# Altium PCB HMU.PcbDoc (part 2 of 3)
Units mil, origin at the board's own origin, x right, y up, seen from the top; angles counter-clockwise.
Board outline 6247.81 x 4035.43 mil, 4 copper layers (Top Layer, Mid-Layer 1, Mid-Layer 2, Bottom Layer), stack 90 mil thick; 310 components, 201 nets, 779 pads, 176 vias.
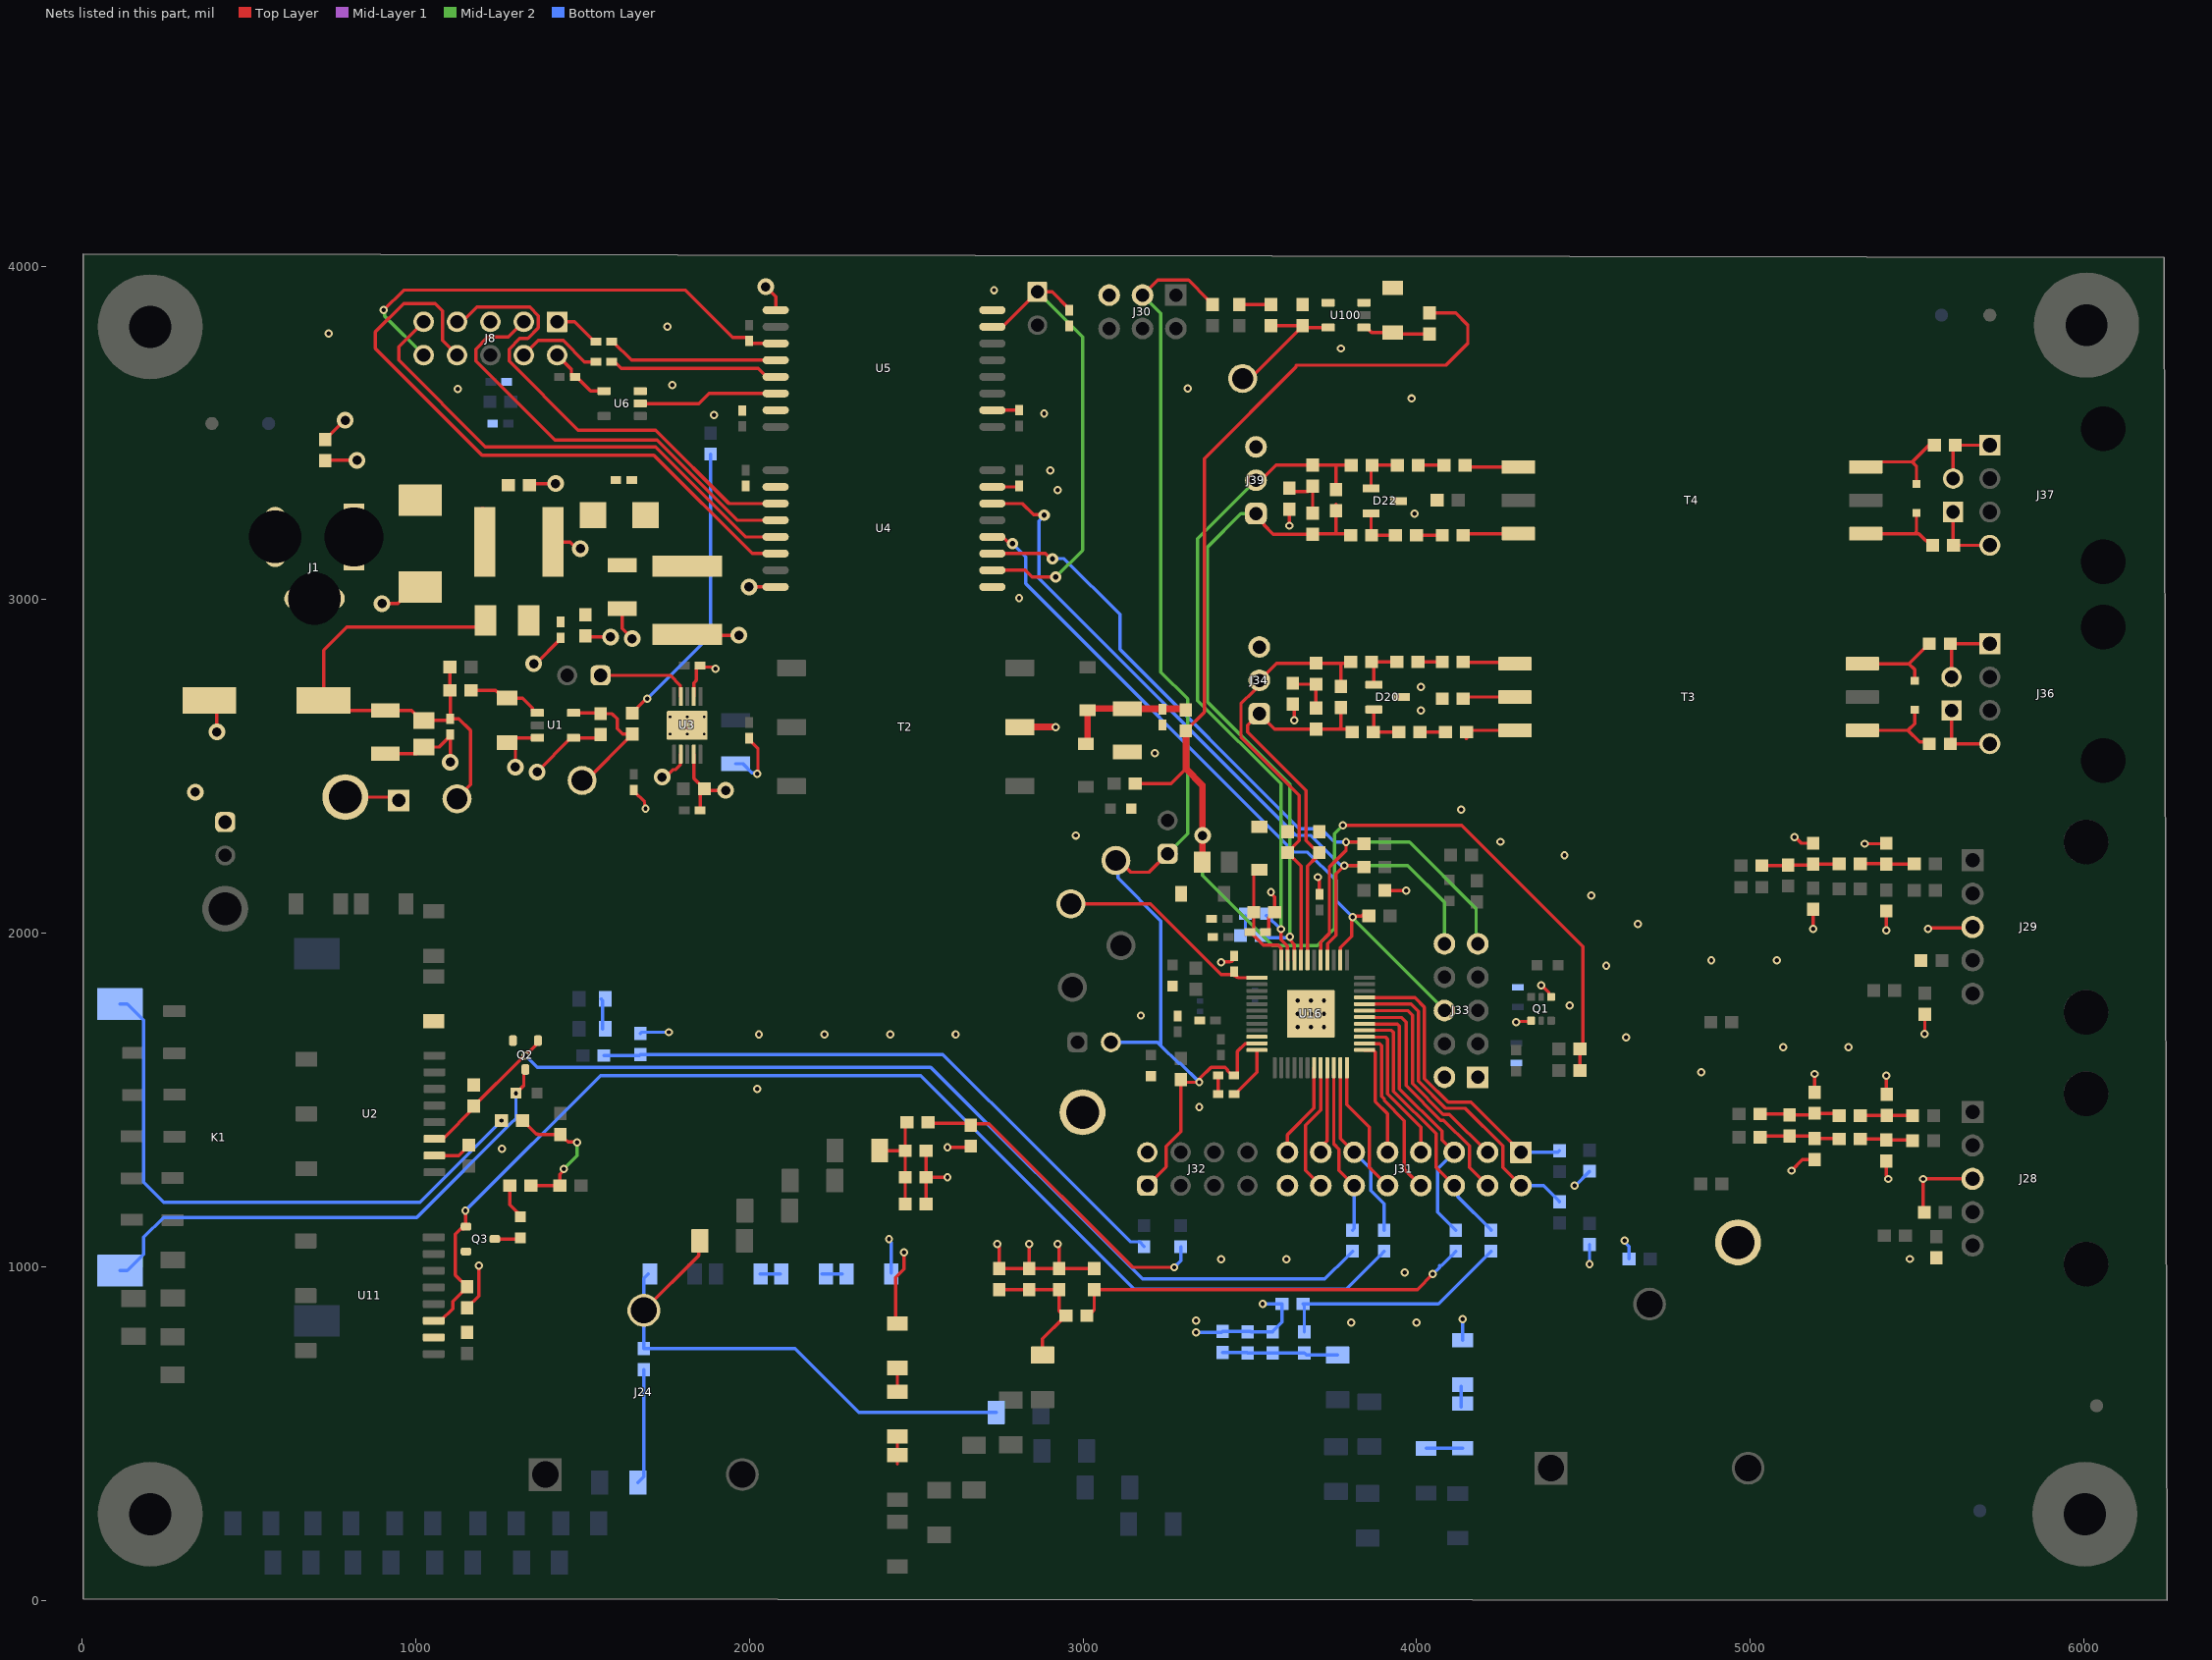
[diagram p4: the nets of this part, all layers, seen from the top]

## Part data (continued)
C100 C106: library part CMP-0007109-5, "CAP, CERM, 0.01 uF, 50 V, +/- 10%, X7R, 0603", Cap_Case=0603, Manufacturer="Samsung Electro-Mechanics", Supplier Part Number 1=1276-1921-1-ND, TempCo=X7R, Tolerance_%=10%, Value1=Unknown, Value2=50V, ValueDisplayed=0.01uF
C108_HV1 C108_HV3 C108_HV4 C109_HV1 C109_HV3 C109_HV4 C110_HV1 C110_HV3 C110_HV4 C500_HV1 C500_HV3 C500_HV4: library part CMP-0008579-2, "CAP, CERM, 1000 pF, 2000 V, +/- 10%, X7R, AEC-Q200 Grade 1, 1206", Cap_Case=1206, Manufacturer=Kemet, Supplier Part Number 1=399-12976-1-ND, TempCo=X7R, Tolerance_%=10%, Value1=Unknown, Value2=2000V, ValueDisplayed=1000pF
C111_HV1 C111_HV3 C111_HV4 C130: library part CMP-0078296-1, "CAP, CERM, 6800 pF, 50 V,+/- 5%, C0G/NP0, 0603", Cap_Case=0603, Manufacturer=MuRata, Supplier Part Number 1=490-11477-1-ND, TempCo=C0G/NP0, Tolerance_%=5%, Value2=50V, ValueDisplayed=6800pF
C112 C113 C114 C115: library part CMP-0077201-1, "CAP, CERM, 2200 pF, 2000 V,+/- 10%, X7R, AEC-Q200 Grade 1, 1206", Cap_Case=1206, Manufacturer="Knowles Capacitors", PartNumber=C1206C102KGRACAUTO, Supplier Part Number 1=1206J2K00222KXR-ND, TempCo=X7R, Tolerance_%=10%, Value2=2000V, ValueDisplayed=22pF
C151: library part CMP-0006350-2, "CAP, CERM, 0.1 uF, 10 V, +/- 10%, X7R, AEC-Q200 Grade 1, 0402", Cap_Case=0402, Manufacturer=MuRata, Supplier Part Number 1=81-GCM155R71A104K5D, TempCo=X7R, Tolerance_%=10%, Value1=Unknown, Value2=10V, ValueDisplayed=0.1uF
D1: library part CMP-0028854-2, "Diode, Schottky, 60 V, 3 A, AEC-Q101, SMA", Manufacturer=Rohm, Value1=3A, Value2=0.64V
D2 D12 D30 D31 D32: library part CMP-0002894-2, "LED, Green, SMD", Color=green, Manufacturer="Wurth Elektronik", Value1=W, Value2=2V
D6 D7: library part CMP-0028525-2, "Diode, Schottky, 30 V, 0.5 A, SOD-123", Manufacturer="ON Semiconductor", Value1=0.5A, Value2=0.43V
D18: library part CMP-0077575-3, "Diode, Zener, 15 V, 500 mW, AEC-Q101, SOD-123", Manufacturer=Vishay-Semiconductor, Power_W=500mW, Value1=0.5W
D19: library part CMP-0005773-4, "Diode, Zener, 12 V, 500 mW, AEC-Q101, SOD-123", Manufacturer=Vishay-Semiconductor, Power_W=500mW, Value1=0.5W
D20 D22: library part CMP-0120582-1, "12-V Bi-directional ESD protection diode in SOT-23", Breakdown Voltage=13.3V, Clamping Voltage=24V, Manufacturer="Texas Instruments", Operating Temperature Range="-40°C to +125°C"
D23 D24: library part CMP-0065114-2, "Diode, TVS, Bi, 8 V, 18.5 Vc, SOD-323", Manufacturer=Bourns, PartNumber=TSD05CDYFR, Value1=400W
D33 D34 D301: library part CMP-0002947-3, "LED, Red, SMD", Color=Red, Manufacturer="Wurth Elektronik", Power_TotalModule=72mW, Value1=0.072W, Value2=2V
D300: library part CMP-0089183-1, "TVS DIODE 36VWM 58.1VC SMC", Breakdown Voltage=40V, Clamping Voltage=58.1V, Digikey Part Number=SMCJ36ALFCT-ND, Manufacturer=Littelfuse, Mouser Part Number=576-SMCJ36A, Operating Temperature Range="-65°C to +150°C"
FID1 FID2 FID3 FID4 FID5 FID6: library part CMP-0077181-1, "Fiducial mark.  There is nothing to buy or mount.", Manufacturer=N/A
H1 H2 H3 H4: library part CMP-0003617-1, "Machine Screw, Round, #4-40 x 1/4, Nylon, Philips panhead", Manufacturer="B&F Fastener Supply", Supplier Part Number 1=H542-ND
H5 H6 H7 H8: library part CMP-0003610-1, "Standoff, Hex, 0.5\"L #4-40 Nylon", Manufacturer=Keystone, Supplier Part Number 1=36-1902C-ND
J1: library part CMP-0091947-1, Current_A=5A, Digikey Part Number=CP-002BH-ND, Manufacturer="CUI Devices", Mouser Part Number=490-PJ-002BH, Operating Temperature Range="-25°C to +85°C", Voltage_V=24V
J5 J10 J11 J21: library part CMP-0077643-1, "Header, 2.54mm, 2x1, Gold, TH", Color=Black, Current_A=5.7A, Manufacturer=Samtec, Supplier Part Number 1=SAM1038-02-ND, Voltage_V=550V
J8: library part CMP-0086439-1, "CONN HEADER 10POS .100 DL R/A AU", Current_A=6.3A, Manufacturer="Wurth Elektronik", PartNumber=61301021021, Voltage_V=550V
J9: library part CMP-0002337-1, "Header, 100mil, 2x1, Tin, TH", Color=Black, Current_A=3A, Manufacturer="Sullins Connector Solutions", Supplier Part Number 1=S1012E-02-ND, Voltage_V=1.8kV
J22 J24: library part CMP-0055525-1, "Terminal Block, 7.5mm, 3x1, R/A, TH", Color=Green, Current_A=41A, Manufacturer="Phoenix Contact", Supplier Part Number 1=277-9875-ND, Voltage_V=1kV
J25: library part CMP-0075403-1, "Header, 100mil, 1pos, Gold, TH", Color=Black, Current_A=6.3A, Manufacturer=Samtec, Supplier Part Number 1=SAM1029-01-ND, Voltage_V=550V
J28 J29: library part 5P_705550039, "Connector Header Through Hole, Right Angle 5 position 0.100\" (2.54mm)", Manufacturer=Molex
J30: library part CMP-0075406-2, "Header, 100mil, 3x2, Gold, TH", Color=Black, Current_A=6.3A, Manufacturer=Samtec, Supplier Part Number 1=SAM1028-03-ND, Voltage_V=550V
J31: library part CMP-0075418-1, "Header, 100mil, 8x2, Gold, TH", Color=Black, Current_A=6.3A, Manufacturer=Samtec, Supplier Part Number 1=SAM1028-08-ND, Voltage_V=550V
J32: library part CMP-0055596-2, "Header, 2.54mm, 4x2, Gold, TH", Color=Black, Current_A=6.3A, Manufacturer=Samtec, Supplier Part Number 1=SAM1040-04-ND, Voltage_V=550V
J33: library part CMP-0075410-2, "Header, 100mil, 5x2, Gold, TH", Color=Black, Current_A=6.3A, Manufacturer=Samtec, Supplier Part Number 1=SAM1028-05-ND, Voltage_V=550V
J34 J39: library part CMP-0075407-2, "Header, 100mil, 3x1, Gold, TH", Color=Black, Current_A=6.3A, Manufacturer=Samtec, Supplier Part Number 1=SAM1029-03-ND, Voltage_V=550V
J35 J38: library part CMP-0075626-1, "Header, 100mil, 2x1, Gold, TH", Color=Black, Manufacturer=Samtec
J36 J37: library part CMP-0055239-1, "Header(shrouded), 2.54mm, 4x1, R/A, Gold, TH", Color=Black, Current_A=3A, Manufacturer=Molex, Supplier Part Number 1=0705510038-ND, Voltage_V=250V
K1: library part CMP-0122333-1, "Reed Relay 5VDC 80Ohm 1.5A SPST-NO(30.2x10.2x8.7)mm SMT", Coil Power_W=313mW, Coil Resistance=80Ω, Coil Voltage_VDC=5V, Contact Rating_A=3A, Manufacturer="Standex Electronics", Operating Temperature Range="-40°C to +100°C", Switching Current=1.5A
L1: library part CMP-0063278-1, "Inductor, Shielded Drum Core, Powdered Iron, 2.2 uH, 2.85 A, 0.08 ohm, SMD", Manufacturer=Vishay-Dale, Supplier Part Number 1=541-1048-1-ND, Value1="0.08 ohm", Value2=2.85A, ValueDisplayed=2.2uH
LBL1: library part CMP-0003625-1, "Thermal Transfer Printable Labels, 0.650\" W x 0.200\" H - 10,000 per roll", Manufacturer=Brady, Supplier Part Number 1=97C5133
Logo2: library part CMP-0074839-1
Logo3: library part CMP-0074847-1, "FCC_disclaimer"
Logo4: library part CMP-0074835-1, "IEC 61010-1 High Voltage Warning"
Logo5: library part CMP-0074769-1
Q1: library part CMP-0089965-1, "Mosfet Array 2 N-Channel (Dual) 60V 300mA 295mW Surface Mount 6-TSSOP", Digikey Part Number=1727-4786-1-ND, Drain To Source Breakdown Voltage=60V, Input Capacitace At Vds="33pF @ 10V", Manufacturer=Nexperia, Mouser Part Number=771-2N7002BKS115, Operating Temperature Range="to +150°C", Power_W=295mW, Pulse Drain Current=1.2A, Typ Forward Diode Voltage=0.75V
Q2 Q3: library part CMP-0750155-1, "MOSFET, N-CH, 60 V, 0.35 A, AEC-Q101, SOT-23", Alternate Manufacturer=None, Manufacturer=Nexperia, Value1="? ohm", Value2="0.5 nC"
R1 R2 R12 R14 R26 R31 R39 R66 R100 R107 R108 R113 R114 R117 R122 R196 R197 R199 R200 R206 R207 R209 R210 R268_HV1 R268_HV3 R268_HV4 R350 R400 R401 R402 R403 R404 R405 R406: library part CMP-0025697-4, "RES, 0, 5%, 0.1 W, AEC-Q200 Grade 0, 0603", Manufacturer=Vishay-Dale, Power_W=100mW, Supplier Part Number 1=541-0.0GCT-ND, TempCo="200 ppm/C", Tolerance_%=5%, Value2=0.1W, Value_Code=0000, ValueDisplayed=0
R3 R4: library part CMP-0065353-2, "RES, 100 k, .5%, .0625 W, 0603", Manufacturer="Susumu Co Ltd", Power_W=62.5mW, Supplier Part Number 1=RR08P100KDCT-ND, TempCo="25 ppm/C", Tolerance_%=0.5%, Value1=.5%, Value2=.0625W, Value_Code=100k
R5 R6 R7 R8 R9 R10 R11 R13 R17 R18: library part CMP-0018591-3, "RES, 150 k, 5%, 0.25 W, AEC-Q200 Grade 0, 1206", Manufacturer=Vishay-Dale, Power_W=250mW, Supplier Part Number 1=541-150KECT-ND, TempCo="200 ppm/C", Tolerance_%=5%, Value2=0.25W, Value_Code=150k
R15 R16: library part CMP-0026875-3, "RES, 20 k, 5%, 0.063 W, AEC-Q200 Grade 0, 0402", Manufacturer=Vishay-Dale, Power_W=63mW, Supplier Part Number 1=541-20KJCT-ND, TempCo="200 ppm/C", Tolerance_%=5%, Value2=0.063W, Value_Code=20k0, ValueDisplayed=20k
R19 R20 R27: library part CMP-0017286-3, "RES, 1.00 M, 1%, 0.25 W, AEC-Q200 Grade 0, 1206", Manufacturer=Panasonic, Power_W=250mW, Supplier Part Number 1=P1.00MFCT-ND, TempCo="100 ppm/C", Tolerance_%=1%, Value2=0.25W, Value_Code=1M00, ValueDisplayed=1.00M
R21: library part CMP-0026768-2, "RES, 100 k, 0.5%, 0.063 W, AEC-Q200 Grade 0, 0402", Manufacturer=Vishay-Dale, Power_W=63mW, Supplier Part Number 1=541-100KAVCT-ND, TempCo="50 ppm/C", Tolerance_%=0.5%, Value2=0.063W, Value_Code=100k
R22 R23: library part CMP-0026824-3, "RES, 100, 5%, 0.063 W, AEC-Q200 Grade 0, 0402", Manufacturer=Vishay-Dale, Power_W=63mW, Supplier Part Number 1=541-100JCT-ND, TempCo="200 ppm/C", Tolerance_%=5%, Value2=0.063W, Value_Code=100R, ValueDisplayed=100
R24 R25: library part CMP-0026825-5, "RES, 10 k, 5%, 0.063 W, AEC-Q200 Grade 0, 0402", Manufacturer=Vishay-Dale, Power_W=63mW, Supplier Part Number 1=541-10KJCT-ND, TempCo="200 ppm/C", Tolerance_%=5%, Value2=0.063W, Value_Code=10k0, ValueDisplayed=10k
R28 R29 R30 R32 R33 R35: library part CMP-0018817-2, "RES, 750 k, 0.1%, 1 W, 1206", Manufacturer="Vishay Draloric", Power_W=1W, Supplier Part Number 1=541-2318-1-ND, TempCo="25 ppm/C", Tolerance_%=0.1%, Value_Code=750k
R34 R67: library part CMP-0025736-4, "RES, 1.0 M, 5%, 0.1 W, AEC-Q200 Grade 0, 0603", Manufacturer=Vishay-Dale, Power_W=100mW, Supplier Part Number 1=541-1.0MGCT-ND, TempCo="200 ppm/C", Tolerance_%=5%, Value2=0.1W, Value_Code=1M00, ValueDisplayed=1.0M
R36 R37: library part CMP-0122375-1, "High-Stability Precision Thin Film Chip Resistor 24.9kOhm .1% 0603", Manufacturer=RESI, Operating Temperature Range="-55°C to +155°C", Power_W=170mW, TempCo=10ppm/°C, Tolerance_%=0.1%
R38 R68 R310 R311 R312: library part CMP-0025769-4, "RES, 2.2 k, 5%, 0.1 W, AEC-Q200 Grade 0, 0603", Manufacturer=Vishay-Dale, Power_W=100mW, Supplier Part Number 1=541-2.2KGCT-ND, TempCo="200 ppm/C", Tolerance_%=5%, Value2=0.1W, Value_Code=2k20, ValueDisplayed=2.2k
R40 R500 R501 R502 R503 R504: library part CMP-0025698-4, "RES, 100 k, 5%, 0.1 W, AEC-Q200 Grade 0, 0603", Manufacturer=Vishay-Dale, Power_W=100mW, Supplier Part Number 1=541-100KGCT-ND, TempCo="200 ppm/C", Tolerance_%=5%, Value2=0.1W, Value_Code=100k
R41 R42: library part CMP-0024912-2, "RES, 200, 0.5%, 0.1 W, 0603", Manufacturer="Yageo America", Power_W=100mW, TempCo="50 ppm/C", Tolerance_%=0.5%, Value2=0.1W, Value_Code=200R, ValueDisplayed=200
R125: library part CMP-0025697-4, "RES, 0, 5%, 0.1 W, AEC-Q200 Grade 0, 0603", Manufacturer=Vishay-Dale, Power_W=100mW, Supplier Part Number 1=541-0.0GCT-ND, TempCo="200 ppm/C", Tolerance_%=5%, Value2=0.1W, Value_Code=0000
R198 R201 R208 R211 R214 R219 R230 R237 R247 R254: library part CMP-0025703-4, "RES, 10, 5%, 0.1 W, AEC-Q200 Grade 0, 0603", Manufacturer=Vishay-Dale, Power_W=100mW, Supplier Part Number 1=541-10GCT-ND, TempCo="200 ppm/C", Tolerance_%=5%, Value2=0.1W, Value_Code=10R0, ValueDisplayed=10
R212 R216: library part CMP-0021998-4, "RES, 10.0 k, 1%, 0.1 W, AEC-Q200 Grade 0, 0603", Manufacturer=Vishay-Dale, Power_W=100mW, Supplier Part Number 1=541-10.0KHCT-ND, TempCo="100 ppm/C", Tolerance_%=1%, Value2=0.1W, Value_Code=10k0, ValueDisplayed=10.0k
R213 R218: library part CMP-0025729-4, "RES, 1.0 k, 5%, 0.1 W, AEC-Q200 Grade 0, 0603", Manufacturer=Vishay-Dale, Power_W=100mW, Supplier Part Number 1=541-1.0KGCT-ND, TempCo="200 ppm/C", Tolerance_%=5%, Value2=0.1W, Value_Code=1k00, ValueDisplayed=1.0k
R220: library part CMP-0020567-3, "RES, 51, 5%, 0.125 W, AEC-Q200 Grade 0, 0805", Manufacturer=Vishay-Dale, Power_W=125mW, Supplier Part Number 1=541-51ACT-ND, TempCo="200 ppm/C", Tolerance_%=5%, Value2=0.125W, Value_Code=51R0, ValueDisplayed=51
R221: library part CMP-0026822-3, "RES, 0, 5%, 0.063 W, AEC-Q200 Grade 0, 0402", Manufacturer=Vishay-Dale, Power_W=63mW, Supplier Part Number 1=541-0.0JCT-ND, TempCo="200 ppm/C", Tolerance_%=5%, Value2=0.063W, Value_Code=0000, ValueDisplayed=0
R228 R229 R235 R236 R245 R246 R252 R253: library part CMP-0025885-5, "RES, 0, 5%, 0.1 W, 0603", Manufacturer=Yageo, Power_W=100mW, Supplier Part Number 1=311-0.0GRCT-ND, TempCo="200 ppm/C", Tolerance_%=5%, Value2=0.1W, Value_Code=0000, ValueDisplayed=0
R231 R238 R248 R255: library part CMP-0025811-4, "RES, 43, 5%, 0.1 W, AEC-Q200 Grade 0, 0603", Manufacturer=Vishay-Dale, Power_W=100mW, Supplier Part Number 1=541-43GCT-ND, TempCo="200 ppm/C", Tolerance_%=5%, Value2=0.1W, Value_Code=43R0, ValueDisplayed=43
R232 R234 R249 R251: library part CMP-0023141-5, "RES, 499, 1%, 0.1 W, 0603", Manufacturer=Yageo, Power_W=100mW, Supplier Part Number 1=311-499HRCT-ND, TempCo="100 ppm/C", Tolerance_%=1%, Value2=0.1W, Value_Code=499R, ValueDisplayed=499
R233 R250: library part CMP-0022109-5, "RES, 1.00 k, 1%, 0.1 W, AEC-Q200 Grade 0, 0603", Manufacturer=Vishay-Dale, Power_W=100mW, Supplier Part Number 1=541-1.00KHCT-ND, TempCo="100 ppm/C", Tolerance_%=1%, Value2=0.1W, Value_Code=1k00, ValueDisplayed=1.00k
R265_HV1 R265_HV3 R265_HV4 R266_HV1 R266_HV3 R266_HV4 R267_HV1 R267_HV3 R267_HV4 R272_HV1 R272_HV3 R272_HV4 R300 R301 R302 R303: library part CMP-0120473-1, "Thick Film High Voltage Chip Resistors 1206 1.5MOhm ±1% ±100ppm/°C", Manufacturer=Bourns, Operating Temperature Range="-55°C to +155°C", Power_W=250mW, TempCo=100ppm/°C, Tolerance_%=1%
R269_HV1 R269_HV3 R269_HV4 R270_HV1 R270_HV3 R270_HV4 R271_HV1 R271_HV3 R271_HV4: library part CMP-0023142-5, "RES, 49.9 k, 1%, 0.1 W, 0603", Manufacturer=Yageo, Power_W=100mW, Supplier Part Number 1=311-49.9KHRCT-ND, TempCo="100 ppm/C", Tolerance_%=1%, Value2=0.1W, Value_Code=49k9, ValueDisplayed=49.9k
T2: library part CMP-0120536-1, "High Clearance and Creepage Transformer", Frequency_Fixed=100-2000kHz, Manufacturer=Bourns, Operating Temperature Range="-40°C to +125°C", Voltage_Isolation_Vrms=7.64kVDC
T3 T4: library part CMP-0122349-1, "SMD BMS Transformer", Manufacturer="LineKey Technology", Operating Temperature Range="-40°C to +125°C", Voltage_Isolation_Vrms=5000VDC
TP1 TP2 TP4 TP5 TP6 TP7 TP100: library part CMP-0055149-1, "Test Point, Multipurpose, White, TH", Color=White, Manufacturer=Keystone, PartNumber=5012, Supplier Part Number 1=36-5012-ND
TP3 TP8 TP9 TP10: library part CMP-0055121-1, "Terminal, Turret, TH, Triple", Manufacturer=Keystone, PartNumber=1598-2, Supplier Part Number 1=36-1598-2-ND
U1 U100: library part CMP-0077329-2, "Automotive High-Voltage Ultra-Low IQ Low-Dropout Regulator/Fixed 5-V Output Voltage, DBV0005A (SOT-23-5)", Alternate Manufacturer="Texas Instruments"
U2 U11: library part CMP-0090961-3, "Isolated Solid State Relay", Manufacturer="Texas Instruments", On State Resistance=85Ω, Operating Temperature Range="-40°C to +150°C", Output Voltage=1400V, Voltage_Isolation_Vrms=1414VDC
U3: library part CMP-0095407-1, "Low-Emission 36V Push-Pull Transformer Driver with Duty Cycle Control for Isolated Power Supplies", Manufacturer="Texas Instruments", Operating Temperature Range="-55°C to +150°C"
U4 U5: library part CMP-0082157-1, "High-Immunity, 5.7kVRMS Reinforced Quad-Channel 3/1 Digital Isolator, 100Mbps, DWW0016A (SOIC-16)", Alternate Manufacturer="Texas Instruments", Alternate PartNumber=ISO7841DWW, Operating Temperature Range="-55 to 125 C"
U6: library part CMP-0051394-2, "Automotive Catalog Single Buffer/Driver With Open-Drain Output, DBV0005A (SOT-23-5)", F @ Nom Voltage(Max)(Mhz)=150, Generic Part Number=SN74LVC1G07-Q1, ICC @ Nom Voltage(Max)(mA)=0.01, Manufacturer="Texas Instruments", Operating Temperature Range="-40 to 125 C", Rating=Automotive, tpd @ Nom Voltage(Max)(ns)=9.8,7,5.7,4.9, Voltage(Nom)(V)=1.8,2.5,3.3,5
U16: library part CMP-0093215-2, "Functional Safety-Compliant Automotive UIR sensor for Battery Junction Box (BJB) and other High Voltge and Current sensing", Manufacturer="Texas Instruments", Max Supply Voltage=18V, Min Supply Voltage=6V, Nominal Supply Current=10mA, Operating Temperature Range="-40°C to +150°C"
ZZ2: library part CMP-0077236-1

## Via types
v1: diameter 24.8, hole 12.99, Top Layer to Bottom Layer, 142 vias
v2: diameter 50, hole 28, Top Layer to Bottom Layer, 19 vias
v3: diameter 34, hole 16, Top Layer to Bottom Layer, 9 vias
v4: diameter 19.68, hole 7.87, Top Layer to Bottom Layer, 6 vias

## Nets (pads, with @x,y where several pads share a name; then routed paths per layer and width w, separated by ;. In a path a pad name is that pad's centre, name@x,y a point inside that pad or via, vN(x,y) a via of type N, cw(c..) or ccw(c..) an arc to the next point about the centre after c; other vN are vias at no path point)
5V_HV: R401.2 R404.1 | length 95
  Top Layer w10: R404.1@3468.27,3884.29 R401.2@3563.27,3884.29
5V_LDO_HV: C301.1 R401.1 TP100.1 U100.5 | length 423.6
  Top Layer w10: TP100.1@3478.27,3662.8 3493,3677.53 3515.48,3677.53 3658.27,3820.31 C301.1@3658.27,3821.3 ; R401.1@3563.27,3822.28 R401.1@3563.27,3821.3 C301.1@3658.27,3821.3 ; C301.1@3658.27,3822.28 C301.1@3658.27,3821.3 ; C301.1@3658.27,3826.3 3669.17,3815.39 U100.5@3734.13,3815.39
5V_LDO_LV: C12.1 R1.1 TP2.1 U1.5 | length 427.9
  Top Layer w10: U1.5@1472.4,2660.2 1550.87,2660.2 C12.1@1553.27,2657.8 1588.27,2657.8 1603.27,2642.8 1603.27,2612.8 1619.76,2596.3 R1.1@1648.27,2596.3 1648.27,2595.31 1510.75,2457.8 TP2.1@1498.27,2457.8
5V_LV: R1.2 R26.1 | length 875.8
  Top Layer w10: R1.2@1648.27,2659.29 1648.27,2660.28 1690.79,2702.8 v1(1693.27,2702.8)
  Bottom Layer w10: v1(1693.27,2702.8) 1883.27,2892.8 R26.1@1883.27,3436.3
12V_HV_J: C300.1 R400.2 U100.1 | length 203.8
  Top Layer w10: U100.1@3842.4,3815.39 3850.28,3815.39 3864.8,3800.87 C300.1@3928.27,3800.87 3932.83,3796.3 R400.2@4038.27,3796.3
24V_LV: C7.1 C8.1 C9.1 C10.1 L1.2 R2.1 R12.1 TP1.1 | length 1530.9
  Top Layer w10: R12.1@1101.77,2797.8 R2.1@1101.77,2727.8 1103.27,2726.3 C9.1@1103.27,2642.8 ; TP1.1@1123.27,2402.8 1123.27,2405.53 1163.27,2445.53 1163.27,2607.8 1128.27,2642.8 C9.1@1103.27,2642.8 ; L1.2@1208.31,2937.8 1188.31,2917.8 793.27,2917.8 723.27,2847.8 C10.1@723.27,2697.8 753.31,2667.76 C7.1@908.27,2667.76 986.81,2667.76 1016.77,2637.8 C8.1@1023.27,2637.8 1098.27,2637.8 C9.1@1103.27,2642.8
24V_LV_J: C13.1 R2.2 U1.1 | length 233.3
  Top Layer w10: R2.2@1159.83,2727.8 1238.27,2727.8 1244.68,2721.38 1246.77,2721.38 1263.27,2704.88 C13.1@1263.27,2702.8 ; C13.1@1270.2,2707.8 C13.1@1273.27,2704.72 1319.61,2704.72 1349.45,2674.88 1349.45,2667.01 1356.26,2660.2 U1.1@1364.13,2660.2
AVDD: C87.1 J11.2 J21.1 J30.3 J32.1 R312.2 R402.1 TP6.1 U16.47 | length 3858
  Top Layer w10: TP6.1@3103.27,2212.8 3113.27,2212.8 3143.56,2182.5 3197.97,2182.5 J21.1@3253.27,2237.8 ; J30.3@3178.27,3912.8 3223.62,3958.15 3316.08,3958.15 3374.57,3899.66 3374.57,3897.99 R402.1@3388.27,3884.29 ; J32.1@3192.64,1242.8 3249.25,1299.41 3249.25,1360.77 3293.27,1404.78 R312.2@3293.27,1561.3 3301.77,1552.8 v1(3348.27,1552.8) 3351.1,1555.63 3351.1,1565.02 3383.57,1597.48 3425.73,1597.48 3433.27,1589.94 3433.27,1587.48 3447.95,1572.8 C87.1@3451.89,1572.8 3455.83,1572.8 3462.64,1579.61 3462.64,1645.41 3485.53,1668.31 3520.32,1668.31 U16.47@3521.22,1669.21
  Mid-Layer 1 w10: J21.1@3253.27,2237.8 J21.1@3278.27,2237.8
  Mid-Layer 2 w10: J30.3@3178.27,3912.8 3232.91,3858.15 3232.91,2782.52 3313.27,2702.16 3313.27,2297.8 J21.1@3253.27,2237.8
  Bottom Layer w10: J11.2@3083.27,1672.8 3223.27,1672.8 3233.27,1662.8 ; TP6.1@3098.27,2217.8 3104.45,2211.61 3104.45,2165.15 3233.27,2036.34 3233.27,1662.8 ; v1(3348.27,1552.8) 3291.85,1609.21 3286.85,1609.21 3233.27,1662.8
BATP: C500_HV1.1 J24.2 R265_HV1.2 R300.2 R406.2 | length 1642.9
  Top Layer w10: J24.2@1683.27,868.86 1847.63,1033.22 1847.63,1074.09 R265_HV1.2@1851.34,1077.8
  Bottom Layer w10: C500_HV1.1@1696.34,977.8 1683.27,964.72 J24.2@1683.27,868.86 R406.2@1683.27,754.29 2136.77,754.29 2328.27,562.8 R300.2@2739.41,562.8
BATP_L: R5.2 R406.1 | length 345.9
  Bottom Layer w10: R5.2@1665.35,352.8 1683.27,370.71 R406.1@1683.27,691.3
COMH_CT: C106.2 R249.1 R251.2 | length 156.5
  Top Layer w10: C106.2@3618.27,3324.29 3673.74,3324.29 R251.2@3688.27,3338.82 ; R249.1@3688.27,3259.29 R251.2@3688.27,3338.82 ; R251.2@3688.27,3339.8 R251.2@3688.27,3338.82
COMHN: C104.1 J39.1 R248.2 R249.2 R250.2 U16.33 | length 2011.7
  Top Layer w10: J39.1@3518.27,3257.8 3518.27,3251.71 3541.6,3228.38 3541.6,3224.47 3569.76,3196.3 R249.2@3688.27,3196.3 ; v1(3619.61,1989.47) 3621.02,1988.05 3621.02,1978.11 3633.43,1965.71 U16.33@3633.43,1919.21 ; R249.2@3688.27,3197.8 3758.27,3197.8 ; 3758.27,3286.3 R250.2@3758.27,3266.3 3758.27,3197.8 ; R248.2@3801.77,3192.8 3796.77,3197.8 3758.27,3197.8
  Mid-Layer 2 w10: J39.1@3518.27,3257.8 3473.27,3257.8 3373.27,3157.8 3373.27,2692.72 3619.61,2446.38 v1(3619.61,1989.47)
  Bottom Layer w10: C104.1@3549.76,1992.8 3555.91,1986.65 3616.79,1986.65 v1(3619.61,1989.47)
COMHN_ISO: J37.4 J38.1 R245.1 | length 209.1
  Top Layer w10: J38.1@5608.27,3262.8 5608.27,3164.29 R245.1@5609.76,3162.8 J37.4@5718.27,3162.8
COMHN_OPT: R246.2 R247.1 | length 77
  Top Layer w10: R247.1@3999.76,3192.8 R246.2@4076.77,3192.8
COMHN_R: D22.2 R247.2 R248.1 | length 137.8
  Top Layer w10: D22.2@3863.27,3257.99 3863.27,3194.29 R248.1@3864.76,3192.8 R247.2@3936.77,3192.8
COMHN_XFMR: R246.1 T4.6 | length 167.4
  Top Layer w10: R246.1@4139.76,3192.8 4144.76,3197.8 4302.99,3197.8 T4.6@4301.5,3199.29
COMHN_XFMR_O: D24.1 R245.2 T4.1 | length 278.8
  Top Layer w10: T4.1@5348.27,3197.8 5493.27,3197.8 ; D24.1@5498.27,3259.49 5498.27,3202.8 5493.27,3197.8 ; R245.2@5546.77,3157.8 5545.79,3157.8 5505.79,3197.8 5493.27,3197.8
COMHP: C107.2 J39.2 R250.1 R251.1 R255.2 U16.34 | length 2075.3
  Top Layer w10: J39.2@3518.27,3342.8 3578.27,3402.8 R251.1@3688.27,3402.8 3758.27,3402.8 ; v1(3592.91,2011.92) 3592.91,1980.41 3612.83,1960.49 3612.83,1920.12 U16.34@3613.74,1919.21 ; R250.1@3758.27,3329.29 3758.27,3402.8 ; R255.2@3809.76,3397.28 3804.25,3402.8 R255.2@3803.27,3402.8 3758.27,3402.8
  Mid-Layer 2 w10: J39.2@3518.27,3357.8 3343.27,3182.8 3343.27,2697.44 3592.91,2447.8 v1(3592.91,2011.92)
  Bottom Layer w10: C107.2@3549.76,2052.8 3550.75,2052.8 3591.62,2011.92 v1(3592.91,2011.92)
COMHP_ISO: J37.1 J38.2 R252.1 | length 206.2
  Top Layer w10: J38.2@5608.27,3362.8 5608.27,3456.3 R252.1@5614.76,3462.8 J37.1@5718.27,3462.8
COMHP_OPT: R253.2 R254.1 | length 77
  Top Layer w10: R254.1@4004.76,3402.8 R253.2@4081.77,3402.8
COMHP_R: D22.1 R254.2 R255.1 | length 146.8
  Top Layer w10: D22.1@3863.27,3332.8 3863.27,3399.8 R255.1@3866.26,3402.8 R254.2@3941.77,3402.8
COMHP_XFMR: R253.1 T4.4 | length 160.3
  Top Layer w10: R253.1@4144.76,3402.8 4149.76,3397.8 T4.4@4302.99,3397.8
COMHP_XFMR_O: D24.2 R252.2 T4.3 | length 301.5
  Top Layer w10: T4.3@5348.27,3397.8 5363.27,3412.8 5486.42,3412.8 ; D24.2@5498.27,3346.1 5498.27,3400.95 5486.42,3412.8 ; R252.2@5546.77,3472.8 5545.79,3472.8 5532.09,3459.09 5532.09,3458.46 5486.42,3412.8
COML_CT: C100.2 R232.1 R234.2 | length 135
  Top Layer w10: C100.2@3635.28,2746.3 R234.2@3698.27,2746.3 R232.1@3698.27,2674.29
COML_XFMR: C99.1 T3.5 | length 148.2
  Top Layer w10: C99.1@4144.76,2707.8 T3.5@4292.99,2707.8
COMLN: C101.2 J34.2 R233.1 R234.1 R238.2 U16.32 | length 1333.3
  Top Layer w10: U16.32@3653.11,1919.21 3653.11,1937.64 3653.27,1937.8 3653.27,2201.3 C101.2@3613.27,2241.3 3613.27,2242.28 3648.27,2277.28 3648.27,2412.8 3473.27,2587.8 3473.27,2687.8 3512.19,2726.72 3512.19,2726.85 3528.27,2742.92 J34.2@3528.27,2757.8 3579.76,2809.29 R234.1@3698.27,2809.29 3768.27,2809.29 ; R233.1@3773.27,2739.29 3773.27,2804.29 3768.27,2809.29 ; R238.2@3801.77,2812.8 3798.27,2809.29 3768.27,2809.29
COMLN_ISO: J35.2 J36.1 R235.1 | length 219.8
  Top Layer w10: J35.2@5603.27,2767.8 5603.27,2864.29 R235.1@5599.76,2867.8 J36.1@5718.11,2867.8
COMLN_OPT: R236.2 R237.1 | length 72.9
  Top Layer w10: R237.1@4003.86,2812.8 R236.2@4076.77,2812.8
COMLN_R: D20.1 R237.2 R238.1 | length 146.7
  Top Layer w10: D20.1@3871.93,2745.2 3871.93,2805.63 R238.1@3864.76,2812.8 R237.2@3940.87,2812.8
COMLN_XFMR: R236.1 T3.4 | length 151.2
  Top Layer w10: R236.1@4143.27,2811.3 4289.49,2811.3 T3.4@4292.99,2807.8
COMLN_XFMR_O: D23.1 R235.2 T3.3 | length 282.3
  Top Layer w10: T3.3@5338.27,2807.8 5475.79,2807.8 ; D23.1@5493.27,2756.1 5493.27,2790.31 5475.79,2807.8 ; R235.2@5536.77,2867.8 5535.79,2867.8 5475.79,2807.8
COMLP: C98.1 J34.1 R231.2 R232.2 R233.2 U16.31 | length 1240.4
  Top Layer w10: U16.31@3672.8,1919.21 3672.8,2200.83 3698.58,2226.61 3699.57,2226.61 3713.27,2240.31 3713.27,2242.28 3699.57,2255.98 3690.08,2255.98 3668.27,2277.8 3668.27,2427.8 3493.27,2602.8 3493.27,2622.8 J34.1@3528.27,2657.8 3574.76,2611.3 R232.2@3698.27,2611.3 3768.27,2611.3 ; R233.2@3773.27,2676.3 3773.27,2617.8 3768.27,2612.8 3768.27,2611.3 ; R231.2@3810.28,2606.3 R231.2@3806.77,2602.8 3798.27,2611.3 3768.27,2611.3
COMLP_ISO: J35.1 J36.4 R228.1 | length 219.8
  Top Layer w10: J35.1@5603.27,2667.8 5603.27,2571.3 R228.1@5599.76,2567.8 J36.4@5718.11,2567.8
COMLP_OPT: R229.2 R230.1 | length 79.1
  Top Layer w10: R230.1@4009.76,2602.8 R229.2@4086.77,2602.8 R229.2@4088.27,2604.29
COMLP_R: D20.2 R230.2 R231.1 | length 145.5
  Top Layer w10: D20.2@3871.93,2670.39 3871.93,2604.96 R231.1@3869.76,2602.8 R230.2@3946.77,2602.8
COMLP_XFMR: R229.1 T3.6 | length 150.3
  Top Layer w10: R229.1@4144.76,2607.8 T3.6@4292.99,2607.8 ; R229.1@4148.27,2584.29 4149.76,2582.8
COMLP_XFMR_O: D23.2 R228.2 T3.1 | length 285
  Top Layer w10: T3.1@5338.27,2607.8 5473.27,2607.8 ; D23.2@5493.27,2669.49 5493.27,2627.8 5473.27,2607.8 ; R228.2@5536.77,2567.8 5531.45,2573.12 5507.94,2573.12 5473.27,2607.8
CP: C91.1 U16.48 | length 162.4
  Top Layer w10: C91.1@3452.64,1517.8 3456.57,1517.8 3521.22,1582.44 U16.48@3521.22,1649.53
CTAP1_HV1: C108_HV1.2 C109_HV1.1 | length 61.1
  Bottom Layer w10: C108_HV1.2@2031.27,977.8 C109_HV1.1@2092.41,977.8
CTAP1_HV3: C108_HV3.2 C109_HV3.1 | length 69.2
  Top Layer w10: 2443.27,408.58 C109_HV3.1@2443.27,477.8
CTAP1_HV4: C108_HV4.2 C109_HV4.1 | length 110.5
  Bottom Layer w10: C108_HV4.2@4028.27,454.72 4029.41,455.87 C109_HV4.1@4138.27,455.87
CTAP2_HV1: C109_HV1.2 C110_HV1.1 | length 61.1
  Bottom Layer w10: C109_HV1.2@2217.13,977.8 C110_HV1.1@2278.27,977.8
CTAP2_HV3: C109_HV3.2 C110_HV3.1 | length 66.1
  Top Layer w10: C109_HV3.2@2443.27,629.72 C110_HV3.1@2443.27,695.87
CTAP2_HV4: C109_HV4.2 C110_HV4.1 | length 61.1
  Bottom Layer w10: C109_HV4.2@4133.27,579.72 C110_HV4.1@4133.27,640.87
DIV_HV1: R268_HV1.2 R269_HV1.2 R270_HV1.2 R271_HV1.2 R272_HV1.1 | length 323.6
  Top Layer w10: R272_HV1.1@2390.2,1347.8 R269_HV1.2@2466.77,1347.8 ; R270_HV1.2@2466.77,1187.8 R271_HV1.2@2466.77,1267.8 R269_HV1.2@2466.77,1347.8 ; R268_HV1.2@2471.77,1432.8 2466.77,1427.8 R269_HV1.2@2466.77,1347.8
DIV_HV3: R268_HV3.2 R269_HV3.2 R270_HV3.2 R271_HV3.2 R272_HV3.1 | length 416
  Top Layer w10: R269_HV3.2@2748.27,931.3 R271_HV3.2@2838.27,931.3 R270_HV3.2@2928.27,931.3 2928.27,866.81 2947.28,847.8 2942.28,847.8 2878.27,783.78 R272_HV3.1@2878.27,734.72
DIV_HV4: R268_HV4.2 R269_HV4.2 R270_HV4.2 R271_HV4.2 R272_HV4.1 | length 348.3
  Bottom Layer w10: R269_HV4.2@3418.27,742.8 3491.77,742.8 R271_HV4.2@3493.27,741.3 R270_HV4.2@3568.27,741.3 R268_HV4.2@3663.27,741.3 3669.84,734.72 R272_HV4.1@3763.27,734.72
DIV_OUT_HV1: C111_HV1.1 R108.2 R268_HV1.1 | length 992
  Top Layer w10: R268_HV1.1@2530.93,1430.14 2660.93,1430.14 2663.27,1427.8 2718.27,1427.8 3148.27,997.8 v1(3273.27,997.8)
  Bottom Layer w10: v1(3273.27,997.8) 3293.27,1017.8 3293.27,1059.17 R108.2@3292.64,1059.8
DIV_OUT_HV3: C111_HV3.1 R114.2 R268_HV3.1 | length 1228.7
  Top Layer w10: R268_HV3.1@3011.26,847.8 3012.24,847.8 3025.94,861.5 3025.94,862.48 3033.27,869.8 C111_HV3.1@3033.27,931.3 4002.05,931.3 v1(4048.27,977.52)
  Bottom Layer w10: v1(4048.27,977.52) 4068.38,997.64 4068.38,1002.64 4073.97,1002.64 4102.95,1031.61 4103.94,1031.61 4117.64,1045.32 R114.2@4117.64,1046.3
DIV_OUT_HV4: C111_HV4.1 R125.2 R268_HV4.1 | length 714.1
  Bottom Layer w10: R268_HV4.1@3663.27,804.29 3663.27,884.29 C111_HV4.1@3659.76,887.8 4065.12,887.8 4222.64,1045.32 R125.2@4222.64,1046.3
DVDD: C88.1 TP5.1 U16.37 | length 655.1
  Top Layer w10: TP5.1@2963.27,2087.8 3201.57,2087.8 3414.13,1875.24 3449.97,1875.24 C88.1@3453.27,1871.94 ; C88.1@3453.27,1879.17 3453.27,1875.24 3456.3,1872.2 3460.08,1868.43 3464.02,1868.43 3466.38,1866.06 U16.37@3521.22,1866.06
EN_6507: J5.1 U3.4 | length 285.2
  Top Layer w10: J5.1@1553.27,2772.8 1762.03,2772.8 1792.68,2742.14 1792.68,2710.31 U3.4@1793.58,2709.41
EN_DISO: J9.1 R25.2 U4.10 U5.7 | length 1442.5
  Top Layer w10: U4.10@2727.87,3087.8 2826.75,3087.8 2846.75,3067.8 v3(2918.27,3067.8) ; U5.7@2728.07,3817.8 2758.27,3817.8 J9.1@2863.27,3922.8 2907.2,3922.8 2958.27,3871.73 R25.2@2958.27,3867.8
  Mid-Layer 1 w10: v3(2918.27,3067.8) v3@2918.27,3068.76
  Mid-Layer 2 w10: J9.1@2863.27,3922.8 2998.27,3787.8 2998.27,3147.8 v3(2918.27,3067.8)
GND: C14.2 C24.2 C25.2 C27.2 C28.2 C49.2 C70.1 C71.1 C74.2 C75.2 C76.1 C77.1 C80.2 C81.2 C82.2 C83.2 C84.2 C85.2 C87.2 C88.2 C89.2 C90.2 C91.2 C92.2 C93.2 C95.2 C98.2 C99.2 C100.1 C101.1 C104.2 C105.2 C106.1 C107.1 C110_HV1.2 C110_HV3.2 C110_HV4.2 C111_HV1.2 C111_HV3.2 C111_HV4.2 C112.2 C130.2 C150.2 C300.2 C301.2 D18.2 D19.2 D20.3 D22.3 D30.1 D31.1 D32.1 J28.3 J29.3 J30.5 J31.16 J32.2 J33.1 J33.2 J34.3 J39.3 Q1.1 Q1.4 Q2.2 Q3.2 R3.1 R4.1 R25.1 R34.1 R36.1 R37.1 R67.1 R214.1 R219.1 R221.2 R269_HV1.1 R269_HV3.1 R269_HV4.1 R270_HV1.1 R270_HV3.1 R270_HV4.1 R271_HV1.1 R271_HV3.1 R271_HV4.1 R405.2 R504.2 T2.5 TP8.1 TP9.1 U2.2 U4.9 U4.15 U5.2 U5.8 U11.2 U16.46 U16.49 U100.3 U100.4 | length 4048.8
  Top Layer w10: U2.2@1055.2,1332.8 1127.76,1332.8 1158.27,1363.31 C14.2@1158.27,1364.29 ; R67.1@1153.27,876.3 1153.27,877.28 1188.27,912.28 v1(1188.27,1002.8) ; C110_HV3.2@2438.27,822.8 2438.27,967.8 2463.27,992.8 v1(2463.27,1042.8) ; R270_HV1.1@2528.27,1179.8 2529.76,1181.3 R270_HV1.1@2529.76,1187.8 R271_HV1.1@2529.76,1267.8 ; R269_HV1.1@2529.76,1347.8 R271_HV1.1@2529.76,1267.8 ; v1(2593.27,1267.8) R271_HV1.1@2529.76,1267.8 ; v1(2593.27,1357.8) 2659.76,1357.8 C111_HV1.2@2663.27,1361.3 ; U4.15@2727.87,3337.8 2805.51,3337.8 C28.2@2808.27,3340.55 ; U5.2@2728.07,3567.8 C27.2@2808.27,3567.8 ; v1(2743.27,1067.8) 2743.27,1063.79 2748.27,1058.79 R269_HV3.1@2748.27,994.29 R271_HV3.1@2838.27,994.29 ; v1(2838.27,1067.8) R271_HV3.1@2838.27,994.29 ; v1(2923.27,1067.8) 2923.27,1063.79 2928.27,1058.79 R270_HV3.1@2928.27,994.29 ; C111_HV3.2@3033.27,994.29 R270_HV3.1@2928.27,994.29 ; C87.2@3404.65,1572.8 3404.65,1518.54 C91.2@3405.39,1517.8 ; v1(3413.27,1912.8) 3414.29,1913.82 3440.67,1913.82 3442.52,1915.67 3446.46,1915.67 3453.27,1922.48 C88.2@3453.27,1926.42 ; C93.2@3556.89,2002.8 3556.89,2045.91 3573.78,2062.8 3573.78,2108.28 3563.27,2118.79 v1(3563.27,2122.8) ; v1(3618.27,3221.57) C106.1@3618.27,3261.3 ; C100.1@3628.27,2686.3 3633.27,2671.3 v1(3633.27,2637.8) ; v1(3703.27,2167.8) 3703.27,2163.79 3708.27,2158.79 C150.2@3708.27,2116.42 ; R504.2@3904.76,2127.8 v1(3968.27,2127.8) ; v1(4298.27,1732.8) 4300.55,1735.08 4341.46,1735.08 Q1.4@4343.74,1737.36 ; v1(4373.27,1842.8) 4375.44,1842.8 4395.98,1822.25 4395.98,1815.04 Q1.1@4402.8,1808.23 ; v1(5123.27,1287.8) 5156.77,1321.3 C74.2@5193.27,1321.3 C74.2@5193.27,1312.8 ; v1(5133.27,2287.8) 5135.01,2287.8 5153.52,2269.29 C76.1@5188.27,2269.29 5188.27,2272.8 C76.1@5193.27,2277.8 ; v1(5188.27,2012.8) C80.2@5188.27,2071.3 ; C70.1@5193.27,1522.8 v1(5193.27,1577.8) ; v1(5343.27,2267.8) 5406.77,2267.8 C77.1@5408.27,2269.29 ; C75.2@5408.27,1316.3 5408.27,1271.8 5413.27,1266.8 v1(5413.27,1262.8) v1@5416.1,1259.96 ; v1(5408.27,1572.8) 5408.27,1517.66 C71.1@5409.63,1516.3 ; v1(5408.27,2007.8) C81.2@5408.27,2066.3 ; v1(5478.27,1022.8) v1@5481.1,1022.8 ; R214.1@5520.79,1162.8 R214.1@5521.77,1162.8 5518.27,1166.3 v1(5518.27,1262.8) 5518.46,1262.99 5666.14,1262.99 J28.3@5666.34,1263.19 ; v1(5523.27,1697.8) C85.2@5523.27,1756.3 ; v1(5533.27,2012.8) 5535.96,2015.49 5663.64,2015.49 J29.3@5666.34,2018.19 ; R271_HV3.1@2838.27,994.29 R270_HV3.1@2928.27,994.29
  Top Layer w20: T2.5@2810.79,2617.8 v1(2918.27,2617.8)
  Bottom Layer w10: R37.1@1554.76,1802.8 1559.76,1797.8 R36.1@1559.76,1712.8 ; C130.2@1673.27,1699.29 1676.77,1702.8 v1(1758.27,1702.8) ; v1(2418.27,1082.8) 2418.27,1078.79 2425.2,1071.86 C110_HV1.2@2425.2,980.51 ; v1(3338.27,802.8) 3415.28,802.8 R269_HV4.1@3418.27,805.79 3501.77,805.79 3503.27,804.29 R270_HV4.1@3568.27,804.29 3568.27,805.28 3596.77,833.78 C111_HV4.2@3596.77,887.8 v1(3538.27,887.8) ; C104.2@3486.77,1992.8 C107.1@3486.77,2052.8 ; C110_HV4.2@4138.27,779.72 v1(4138.27,842.8) ; v1(4473.27,1242.8) 4475.75,1242.8 4518.27,1285.31 C84.2@4518.27,1286.3 ; v1(4518.27,1007.8) C82.2@4518.27,1066.3 ; v1(4623.27,1077.8) 4623.27,1073.79 4636.77,1060.29 R405.2@4636.77,1022.8
  other v1: 3803.27,832.8 3999.93,832.8 3338.27,837.8 3964.76,982.19 3413.27,1021.62 3609.93,1021.62 1258.27,1352.8 3348.27,1477.8 2023.27,1532.8 4853.27,1582.8 5098.27,1657.8 5294.93,1657.8 4628.27,1687.8 2028.27,1696.62 2224.93,1696.62 2421.6,1696.62 2618.27,1696.62 3643.27,1718.43 3682.64,1718.43 3722.01,1718.43 3173.27,1752.8 3643.27,1757.8 3682.64,1757.8 3722.01,1757.8 4458.27,1782.8 3643.27,1797.17 3682.64,1797.17 3722.01,1797.17 4568.27,1902.8 4883.27,1917.8 5079.93,1917.8 4663.27,2027.8 4523.27,2112.8 4443.27,2232.8 4250.96,2273.8 2978.27,2292.8 4133.27,2369.97 3215.58,2538.8 4013.27,2667.8 4013.27,2737.8 2808.27,3004.97 3993.27,3257.8 2923.27,3327.8 2901.65,3386.62 2883.27,3557.8 3984.93,3602.8 3313.27,3632.8 3773.27,3752.8 2733.27,3927.8
GND_ISO: C29.2 C30.2 C31.2 C151.1 J8.5 R31.2 U4.2 U4.8 U5.9 U5.15 U6.3 | length 249.3
  Top Layer w10: R31.2@728.27,3479.29 728.27,3480.28 785.79,3537.8 v2(788.27,3537.8) ; C30.2@1976.89,3567.8 C30.2@1978.27,3566.42 ; v2(1998.27,3037.8) U4.8@2078.27,3037.8 ; v2(2048.27,3937.8) 2078.46,3907.6 U5.9@2078.46,3867.8
  other v1: 1893.27,3552.8 1125.96,3631.79 1768.27,3642.8 738.27,3797.8 1753.27,3817.8
GND_LV: C1.2 C2.2 C3.2 C4.2 C5.2 C6.2 C7.2 C8.2 C9.2 C10.2 C12.2 C13.2 C21.2 C22.2 C23.2 C26.2 D300.2 J1.2 J1.3 J10.1 J25.1 R15.1 R16.1 R31.1 TP3.1 U1.3 U1.4 U3.2 U3.7 U3.9 U3.11 | length 2621.4
  Top Layer w10: C10.2@372.64,2697.8 C10.2@380.75,2697.8 403.27,2675.28 v2(403.27,2602.8) ; R31.1@728.27,3416.3 729.76,3417.8 v2(823.27,3417.8) ; TP3.1@788.27,2407.8 938.27,2407.8 J25.1@948.27,2397.8 ; v2(898.27,2987.8) 945.47,2987.8 995.55,3037.87 D300.2@1013.27,3037.87 ; C7.2@908.27,2537.83 1003.31,2537.83 C8.2@1023.27,2557.8 1069.45,2557.8 C9.2@1103.27,2591.61 ; v2(1103.27,2512.8) C9.2@1103.27,2591.61 ; C9.2@1103.27,2595.55 C9.2@1103.27,2591.61 ; v2(1298.27,2497.8) 1298.27,2555.71 1283.11,2570.87 C13.2@1273.27,2570.87 1287.8,2585.39 U1.3@1364.13,2585.39 ; C1.2@1339.76,3342.8 1344.76,3347.8 v2(1418.27,3347.8) ; v2(1353.27,2807.8) 1359.45,2807.8 1433.27,2881.61 C6.2@1433.27,2885.55 ; v2(1363.27,2482.8) 1363.27,2484.13 1464.53,2585.39 U1.4@1472.4,2585.39 1543.86,2585.39 C12.2@1553.27,2594.8 ; C2.2@1410.63,3172.8 1462.44,3172.8 1482.44,3152.8 v2(1493.27,3152.8) ; C5.2@1508.27,2891.3 1511.77,2887.8 v2(1583.27,2887.8) ; C4.2@1618.27,2972.83 1618.27,2912.8 v2(1648.27,2882.8) ; R16.1@1653.27,2429.17 1653.27,2425.24 1685.44,2393.07 1685.44,2375.63 v1(1688.27,2372.8) ; v2(1738.27,2467.8) 1749.09,2467.8 1771.53,2490.24 1779.47,2490.24 1792.68,2503.45 1792.68,2535.28 U3.7@1793.58,2536.18 ; C3.2@1813.27,2895.43 1815.91,2892.8 v2(1968.27,2892.8) ; U3.9@1832.95,2536.18 1832.95,2463.62 1863.78,2432.8 C26.2@1864.76,2432.8 ; U3.2@1832.95,2709.41 1832.95,2749.77 1841.14,2757.96 1841.14,2790.98 1847.95,2797.8 1851.89,2797.8 1889.26,2797.8 1894.26,2792.8 v1(1898.27,2792.8) ; R15.1@1851.89,2367.8 1851.89,2419.92 C26.2@1864.76,2432.8 ; v2(1928.27,2427.8) 1869.76,2427.8 C26.2@1864.76,2432.8 ; C22.2@1998.27,2584.17 1998.27,2580.24 2025.44,2553.07 2025.44,2479.96 v1(2023.27,2477.8)
  Bottom Layer w10: C21.2@1958.27,2507.83 1979.92,2507.83 2007.13,2480.63 2020.44,2480.63 v1(2023.27,2477.8)
  other v2: 338.27,2422.8
  other v4: 1762.09,2597.2 1813.27,2597.2 1864.45,2597.2 1762.09,2648.39 1813.27,2648.39 1864.45,2648.39
GPIO1: J31.1 R122.1 U16.21 | length 904
  Top Layer w10: U16.21@3844.06,1807.01 3844.58,1806.48 3994.58,1806.48 4023.27,1777.8 4023.27,1563.65 4094.38,1492.54 4162.89,1492.54 J31.1@4312.64,1342.8
  Bottom Layer w10: J31.1@4312.64,1342.8 4423.27,1342.8 R122.1@4428.27,1347.8
GPIO2: J31.2 R117.1 U16.20 | length 990.7
  Top Layer w10: U16.20@3844.06,1787.32 3983.74,1787.32 4005.39,1765.67 4005.39,1556.25 4086.98,1474.67 4144.9,1474.67 4257.99,1361.58 4257.99,1297.44 J31.2@4312.64,1242.8
  Bottom Layer w10: J31.2@4312.64,1242.8 4380.75,1242.8 4428.27,1195.28 R117.1@4428.27,1194.29
GPIO3: J31.3 U16.19 | length 664.5
  Top Layer w10: U16.19@3844.06,1767.64 3973.43,1767.64 3987.52,1753.54 3987.52,1548.85 4079.57,1456.8 4098.64,1456.8 J31.3@4212.64,1342.8
GPIO4: J31.4 U16.18 | length 726.7
  Top Layer w10: U16.18@3844.06,1747.95 3844.96,1747.05 3877.44,1747.05 3954.02,1747.05 3968.27,1732.8 3968.27,1542.82 4072.17,1438.92 4080.65,1438.92 4157.99,1361.58 4157.99,1297.44 J31.4@4212.64,1242.8
GPIO5: J31.5 R114.1 U16.17 | length 830.3
  Top Layer w10: U16.17@3844.06,1728.27 3844.96,1727.36 3942.41,1727.36 3948.27,1721.5 3948.27,1533.35 4075.87,1405.75 4075.87,1379.57 J31.5@4112.64,1342.8
  Bottom Layer w10: J31.5@4112.64,1342.8 4063.27,1293.43 4063.27,1163.66 R114.1@4117.64,1109.29
GPIO6: J31.6 R125.1 U16.16 | length 803.2
  Top Layer w10: U16.16@3844.06,1708.58 3924.54,1708.58 3930.39,1702.72 3930.39,1525.95 4057.99,1398.35 4057.99,1297.44 J31.6@4112.64,1242.8
  Bottom Layer w10: J31.6@4112.64,1242.8 4123.15,1232.28 4123.15,1209.76 4222.64,1110.28 R125.1@4222.64,1109.29
GPIO7: J31.7 U16.15 | length 452.1
  Top Layer w10: U16.15@3844.06,1688.9 3844.96,1687.99 3874.15,1687.99 3906.66,1687.99 3912.52,1682.13 3912.52,1518.54 4012.64,1418.43 J31.7@4012.64,1342.8
GPIO8: J31.8 U16.14 | length 521.9
  Top Layer w10: U16.14@3844.06,1669.21 3844.96,1668.31 3888.79,1668.31 3894.65,1662.45 3894.65,1511.14 3903.27,1502.52 3903.27,1497.8 3963.27,1437.8 3963.27,1292.17 J31.8@4012.64,1242.8
GPIO9: J31.9 U16.13 | length 350.1
  Top Layer w10: U16.13@3844.06,1649.53 3869.65,1649.53 3875.87,1643.31 3875.87,1495.2 3912.64,1458.43 J31.9@3912.64,1342.8
GPIO10: J31.10 U16.12 | length 404.1
  Top Layer w10: U16.12@3790.91,1596.38 3790.91,1485.16 3858.27,1417.8 3857.99,1297.44 J31.10@3912.64,1242.8
GPIO11: J31.11 R107.1 U16.11 | length 541.5
  Top Layer w10: U16.11@3771.22,1596.38 3771.22,1384.21 J31.11@3812.64,1342.8
  Bottom Layer w10: J31.11@3812.64,1342.8 3862.9,1292.54 3862.9,1228.4 3902.64,1188.65 R107.1@3902.64,1109.29
GPIO12: J31.12 R113.1 U16.10 | length 515.2
  Top Layer w10: U16.10@3751.54,1596.38 3751.54,1573.7 3750.63,1572.8 3751.54,1571.89 3751.54,1368.04 3767.28,1352.29 3767.28,1288.15 J31.12@3812.64,1242.8
  Bottom Layer w10: R113.1@3807.64,1109.29 3812.64,1114.29 J31.12@3812.64,1242.8
GPIO13: J31.13 U16.9 | length 261.5
  Top Layer w10: J31.13@3712.64,1342.8 3712.64,1357.67 3731.85,1376.88 U16.9@3731.85,1596.38
GPIO14: J31.14 U16.8 | length 391
  Top Layer w10: U16.8@3712.17,1596.38 3712.17,1469.39 3667.28,1424.5 3667.28,1288.15 J31.14@3712.64,1242.8
GPIO15: J31.15 U16.7 | length 286.7
  Top Layer w10: J31.15@3612.64,1342.8 3612.64,1395.14 3692.48,1474.98 U16.7@3692.48,1596.38
HS_SW_DRV: Q3.1 R67.2 R107.2 U11.3 | length 3652.1
  Top Layer w10: U11.3@1053.27,837.8 1073.94,837.8 1110.16,874.02 1110.16,895.2 1153.27,938.31 R67.2@1153.27,939.29 1118.27,974.29 1118.27,1097.8 1134.42,1113.94 1143.71,1113.94 Q3.1@1149.96,1120.2 1149.11,1121.04 1149.11,1166.95 v1(1148.27,1167.8)
  Bottom Layer w10: v1(1148.27,1167.8) 1553.27,1572.8 2513.27,1572.8 3153.27,932.8 3789.13,932.8 3887.95,1031.61 3888.94,1031.61 3902.64,1045.32 R107.2@3902.64,1046.3
HV12: R14.2 R41.2 R42.2 R220.1 R310.2 R400.1 | length 4717.8
  Top Layer w10: R310.2@3156.26,2447.8 3263.27,2447.8 3308.27,2492.8 ; R14.2@3308.27,2606.3 3308.27,2607.28 3363.27,2662.28 3363.27,3422.8 3638.27,3697.8 ; 3638.27,3702.8 4088.27,3702.8 4153.27,3767.8 4153.27,3822.8 4116.77,3859.29 R400.1@4038.27,3859.29 ; v1(3778.27,2322.8) 4134.48,2322.8 4498.27,1959 4498.27,1661.3 R41.2@4489.76,1652.8 R42.2@4489.76,1587.8
  Top Layer w20: R14.2@3308.27,2606.3 3308.27,2492.8 3357.64,2443.43 R220.1@3357.64,2212.8
  Mid-Layer 2 w10: v2@3358.27,2282.8 3358.27,2172.8 3568.27,1962.8 3702.41,1962.8 3753.27,2013.65 3753.27,2297.8 v1(3778.27,2322.8)
  other v2: 3358.27,2292.8
ISO_MISO_TX: J8.8 U4.6 | length 1901.4
  Top Layer w10: J8.8@1123.27,3732.8 1079.49,3776.57 1079.49,3865.72 1057.41,3887.8 963.27,3887.8 878.27,3802.8 878.27,3752.8 1198.27,3432.8 1713.27,3432.8 2008.27,3137.8 U4.6@2078.27,3137.8
ISO_MOSI_RX: J8.7 U4.3 | length 1434.6
  Top Layer w10: J8.7@1123.27,3832.8 1133.18,3842.71 1149.4,3842.71 1183.27,3876.57 1341.4,3876.57 1367.05,3850.93 1367.05,3814.66 1335.18,3782.8 1311.35,3782.8 1279.49,3750.93 1279.49,3714.66 1486.35,3507.8 1718.55,3507.8 1721.47,3504.87 1938.55,3287.8 U4.3@2078.27,3287.8
ISO_nCS: J8.9 U4.5 | length 1495.6
  Top Layer w10: J8.9@1023.27,3832.8 948.27,3757.8 948.27,3717.8 1208.27,3457.8 1717.99,3457.8 1987.99,3187.8 U4.5@2078.27,3187.8
ISO_nFAULT: U5.14 U6.2 | length 418.5
  Top Layer w10: U6.2@1672.4,3587.8 1848.27,3587.8 1878.27,3617.8 U5.14@2078.46,3617.8
ISO_nFAULT_OD: J8.2 R21.1 U6.4 | length 194.7
  Top Layer w10: J8.2@1423.27,3732.8 1466.14,3689.92 1466.14,3669.61 R21.1@1472.42,3663.33 ; R21.1@1476.89,3667.8 1480.83,3667.8 1523.43,3625.2 U6.4@1564.13,3625.2
ISO_nUART_SPI: J8.10 R24.1 U5.11 | length 1455
  Top Layer w10: v1(903.27,3867.8) 963.27,3927.8 1808.27,3927.8 1950,3786.06 1991.46,3786.06 R24.1@1993.94,3783.58 ; J8.10@1015.45,3740.61 J8.10@1023.27,3732.8 ; R24.1@1998.27,3775.55 1998.27,3774.61 2005.08,3767.8 U5.11@2078.46,3767.8
  Mid-Layer 2 w10: v1(903.27,3867.8) 906.1,3864.96 906.1,3849.96 J8.10@1023.27,3732.8
ISO_OC1: R22.2 U5.13 | length 505.2
  Top Layer w10: R22.2@1591.89,3712.8 1595.83,3712.8 1615.83,3692.8 2025.91,3692.8 2050.91,3667.8 U5.13@2078.46,3667.8
ISO_OC1_R: J8.4 R22.1 | length 265.9
  Top Layer w10: J8.4@1323.27,3732.8 1367.05,3776.57 1441.4,3776.57 1505.18,3712.8 R22.1@1544.65,3712.8
ISO_OC2: R23.2 U5.12 | length 514.4
  Top Layer w10: R23.2@1586.89,3772.8 1590.83,3772.8 1645.83,3717.8 U5.12@2078.46,3717.8
ISO_OC2_R: J8.1 R23.1 | length 141.2
  Top Layer w10: J8.1@1423.27,3832.8 1475.71,3832.8 1535.71,3772.8 R23.1@1539.65,3772.8
ISO_SCLK: J8.3 U4.4 | length 1310.3
  Top Layer w10: J8.3@1323.27,3832.8 1277.38,3786.91 1215.46,3786.91 1179.49,3750.93 1179.49,3714.66 1416.35,3477.8 1723.27,3477.8 1963.27,3237.8 U4.4@2078.27,3237.8
ISO_VN: C130.1 R66.1 R100.2 | length 1860.2
  Bottom Layer w10: R66.1@1563.27,1632.8 1669.76,1632.8 C130.1@1673.27,1636.3 2579.76,1636.3 2863.27,1352.8 3141.57,1074.49 3168.94,1074.49 3182.64,1060.79 R100.2@3182.64,1059.8
KL30_IN: C1.1 C2.1 C11.2 D1.2 D300.1 J1.1 | length 92.9
  Top Layer w10: D1.2@1530.79,3252.8 D1.2@1535.71,3257.72 ; C11.2@1595.71,3357.8 C11.2@1599.65,3357.8
  Top Layer w50: C2.1@1199.41,3252.13 1205.91,3245.63 C2.1@1205.91,3172.8
KL30_PROTECT: C3.1 C4.1 C5.1 C6.1 C11.1 D1.1 L1.1 | length 8.6
  Top Layer w10: C6.1@1433.27,2932.8 C6.1@1433.27,2936.73 ; C5.1@1508.27,2954.29 C5.1@1508.27,2955.28 ; C3.1@1810.67,3102.76 C3.1@1813.27,3100.16
LDOCAP: C92.1 C93.1 D19.1 U16.35 | length 344.6
  Top Layer w10: C93.1@3499.65,2002.8 3503.58,2002.8 3510.39,1995.98 3510.39,1993.53 3518.27,1985.65 3540.34,1963.58 3584.47,1963.58 3593.15,1954.9 3593.15,1920.12 U16.35@3594.06,1919.21 ; C93.1@3511.77,2004.92 C92.1@3511.77,2062.8 3511.77,2176.77 3524.78,2189.78 D19.1@3528.27,2189.78
LED_5V_TPSI: R38.2 R39.1 R68.2 R350.2 | length 429.3
  Top Layer w10: R39.1@1319.76,1437.8 1320.75,1437.8 1360.75,1397.8 1364.76,1397.8 1366.26,1396.3 R38.2@1433.27,1396.3 1433.27,1395.31 1446.97,1381.61 1447.95,1381.61 1455.87,1373.7 1482.36,1373.7 v1(1483.27,1372.8) ; R68.2@1344.76,1242.8 R350.2@1431.77,1242.8 1431.77,1277.29 1443.27,1288.79 v1(1443.27,1292.8)
  Mid-Layer 2 w10: v1(1443.27,1292.8) 1483.27,1332.8 v1(1483.27,1372.8)
LED_SW: D12.1 Q3.3 | length 87.3
  Top Layer w10: Q3.3@1236.57,1082.8 1321.77,1082.8 D12.1@1323.27,1081.3
LED_SW2: D2.1 K1.2 Q2.3 | length 1570.6
  Top Layer w10: v1(1299.88,1520) 1323.27,1543.39 1323.27,1591.21 Q2.3@1323.27,1599.49
  Bottom Layer w10: K1.2@112.72,988.19 134.37,988.19 183.27,1037.09 183.27,1087.8 243.27,1147.8 1002.52,1147.8 1282.52,1427.8 1283.27,1427.8 1299.88,1444.41 v1(1299.88,1520)
LED_SW_R: D12.2 R68.1 | length 115.7
  Top Layer w10: R68.1@1281.77,1242.8 1281.77,1185.79 D12.2@1323.27,1144.29
LED_SW_R2: K1.1 R39.2 | length 1776.4
  Bottom Layer w10: K1.1@112.72,1787.4 134.37,1787.4 183.27,1738.5 183.27,1252.8 243.27,1192.8 1011.77,1192.8 v1(1256.77,1437.8)
LS_SW_DRV: Q2.1 R34.2 R113.2 U2.3 | length 3227.7
  Top Layer w10: U2.3@1060.2,1382.8 1080.87,1382.8 R34.2@1175.83,1477.76 ; R34.2@1173.27,1481.3 1173.27,1482.28 1186.97,1495.98 1187.95,1495.98 1298.58,1606.61 1324.76,1632.8 v1(1328.27,1632.8) 1359.42,1663.94 1359.42,1680.42 Q2.1@1360.67,1681.68
  Bottom Layer w10: v1(1328.27,1632.8) 1363.27,1597.8 2543.27,1597.8 3178.27,962.8 3724.13,962.8 3792.95,1031.61 3793.94,1031.61 3807.64,1045.32 R113.2@3807.64,1046.3
MISO_TX: J33.9 R500.1 U4.11 U16.29 | length 2514.9
  Top Layer w10: U4.11@2727.87,3137.8 2886.77,3137.8 2901.77,3122.8 v3(2908.27,3122.8) ; U16.29@3712.17,1919.21 3712.17,1972.52 3738.27,1998.63 3738.27,2197.8 3788.27,2247.8 v1(3788.27,2272.8) 3836.77,2272.8 R500.1@3841.77,2267.8
  Mid-Layer 1 w10: J33.9@4178.27,1979.57 J33.9@4188.27,1969.57
  Mid-Layer 2 w10: v1(3788.27,2272.8) 3978.27,2272.8 4178.27,2072.8 4178.27,1972.8 J33.9@4183.27,1967.8
  Bottom Layer w10: v3(2908.27,3122.8) 2943.27,3122.8 3110.39,2955.67 3110.39,2850.67 3648.27,2312.8 3713.27,2312.8 3753.27,2272.8 v1(3788.27,2272.8)
MOSI_RX: J33.10 R501.1 U4.14 U16.28 | length 2468.3
  Top Layer w10: U4.14@2727.87,3287.8 2818.01,3287.8 2851.27,3254.54 2881.52,3254.54 v3(2883.27,3252.8) ; U16.28@3731.85,1919.21 3732.76,1920.12 3732.76,1967.84 3734.57,1969.65 3757.99,1993.07 3757.99,2177.52 v1@3779.71,2199.23 ; v1(3783.27,2202.8) 3836.77,2202.8 R501.1@3841.77,2197.8
  Mid-Layer 2 w10: v1(3783.27,2202.8) 3973.27,2202.8 4083.27,2092.8 J33.10@4083.27,1967.8
  Bottom Layer w10: v3(2883.27,3252.8) 2883.27,3249.94 2868.27,3234.94 2868.27,3062.8 3638.27,2292.8 3683.27,2292.8 3770.44,2205.63 3780.44,2205.63 v1(3783.27,2202.8)
nCS: J33.6 R502.1 U4.12 U16.26 | length 2208.4
  Top Layer w10: U4.12@2727.87,3187.8 2759.12,3187.8 2774.53,3172.39 2783.68,3172.39 v3(2788.27,3167.8) ; U16.26@3771.22,1919.21 3771.69,1919.68 3771.69,1956.22 3805.44,1989.96 3805.44,2044.96 v1(3808.27,2047.8) ; v1@3811.1,2050.63 3834.6,2050.63 R502.1@3841.77,2057.8
  Mid-Layer 1 w10: J33.6@4083.27,1767.8 J33.6@4083.27,1770.3
  Mid-Layer 2 w10: v1(3808.27,2047.8) 3808.27,2045.3 4083.27,1770.3 J33.6@4083.27,1767.8
  Bottom Layer w10: v3(2788.27,3167.8) 2828.27,3127.8 2828.27,3047.8 3633.27,2242.8 3672.99,2242.8 3757.99,2157.79 3757.99,2098.07 v1(3808.27,2047.8)
NetC24_1: C24.1 C25.1 D6.1 D7.1 R14.1 | length 397.1
  Top Layer w20: D7.1@3013.27,2560.11 3013.27,2673.33 3087.19,2673.33 ; C24.1@3093.31,2672.8 C24.1@3133.27,2672.76 3203.27,2672.8 3238.27,2672.8 R14.1@3303.27,2672.8
NetC70_2: C70.2 C72.1 R196.1 R197.2 | length 243.6
  Top Layer w10: R196.1@5029.76,1457.8 5114.7,1457.8 C72.1@5118.2,1454.29 5187.76,1454.29 C70.2@5193.27,1459.8 5259.76,1459.8 R197.2@5266.77,1452.8
NetC71_2: C71.2 R197.1 R198.1 | length 157.4
  Top Layer w10: R197.1@5329.76,1452.8 5409.12,1452.8 C71.2@5409.63,1453.31 5486.26,1453.31 R198.1@5486.77,1452.8
NetC72_2: C72.2 C74.1 R199.1 R200.2 | length 244.1
  Top Layer w10: R199.1@5029.76,1387.8 5033.27,1391.3 C72.2@5118.2,1391.3 5186.26,1391.3 C74.1@5193.27,1384.29 5265.28,1384.29 R200.2@5266.77,1382.8 R200.2@5265.28,1381.3
NetC75_1: C75.1 R200.1 R201.1 | length 161.2
  Top Layer w10: R200.1@5329.76,1382.8 5404.76,1382.8 C75.1@5408.27,1379.29 5485.28,1379.29 R201.1@5486.77,1377.8 R201.1@5485.28,1376.3
NetC76_2: C76.2 C78.1 R206.1 R207.2 | length 234.1
  Top Layer w10: R206.1@5034.76,2202.8 5111.71,2202.8 C78.1@5113.2,2204.29 5186.26,2204.29 C76.2@5188.27,2206.3 5265.28,2206.3 R207.2@5266.77,2207.8
NetC77_2: C77.2 R207.1 R208.1 | length 163.2
  Top Layer w10: R207.1@5329.76,2207.8 5406.77,2207.8 C77.2@5408.27,2206.3 5490.28,2206.3 R208.1@5491.77,2207.8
